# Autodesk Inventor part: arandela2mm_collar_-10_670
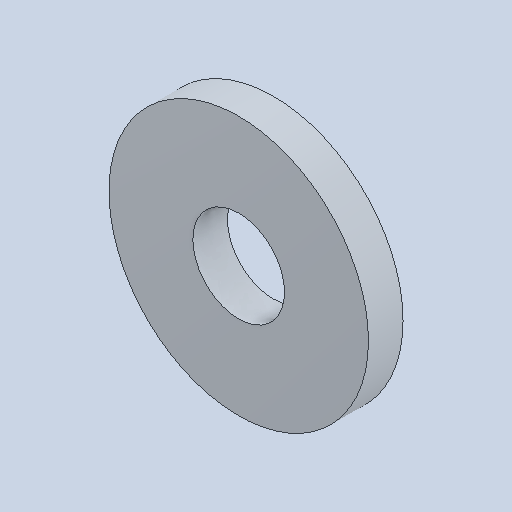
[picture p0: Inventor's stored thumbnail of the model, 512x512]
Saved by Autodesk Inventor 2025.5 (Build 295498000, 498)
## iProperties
Created: 2026-10
Part Number: arandela2mm_collar_-10_670
Material: Genérico
Document SubType Name: Modeling
Designer: Luis M
Density: 1 g/cm^3
Appearance: Valor por defecto
Author: Luis M
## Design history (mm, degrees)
feature "Base1"
node "Sólido1"
